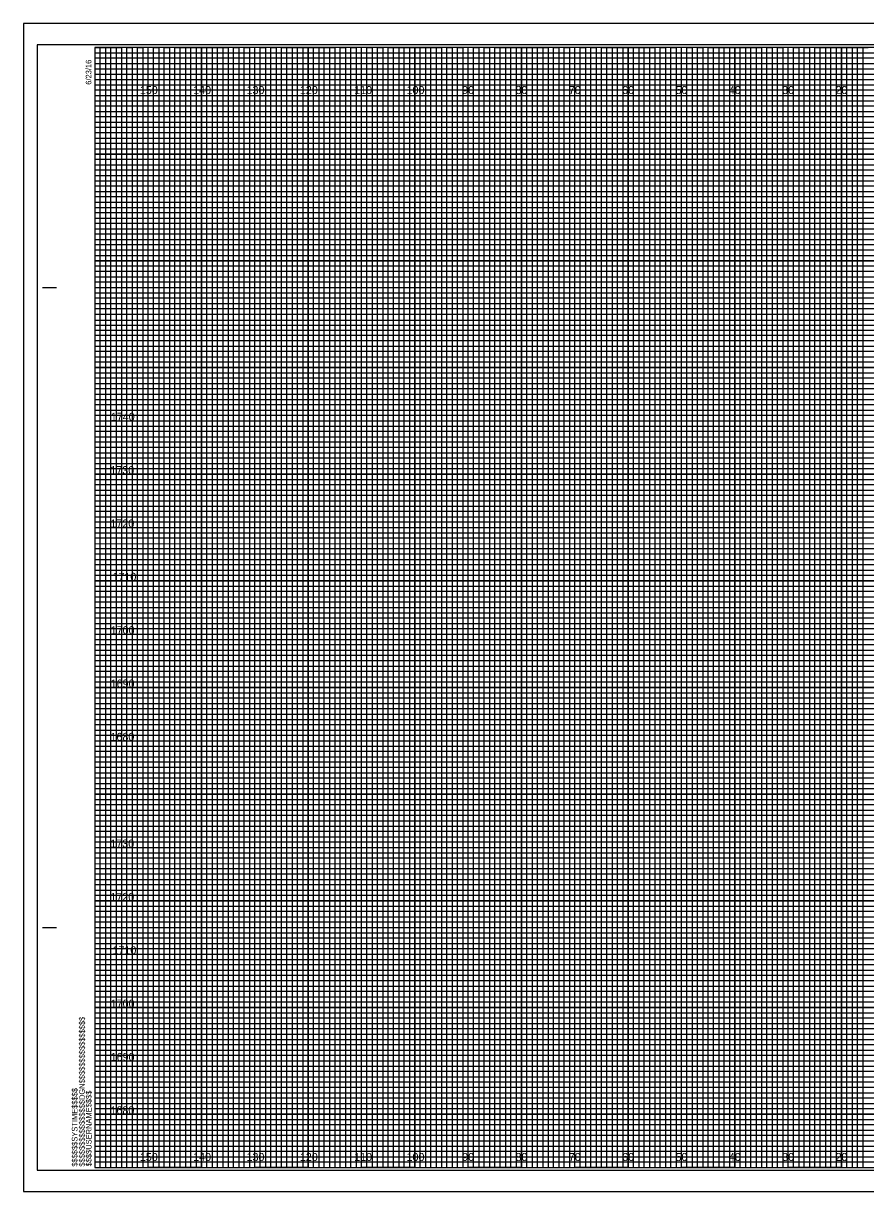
# Model space of a CAD drawing. Extents: x 656 to 993, y -2 to 2857.
# Drawn here: x 656.3 to 814.2, y 2638.3 to 2857.3 of the extents above; entities that cross this region are included whole.
import ezdxf

# ---------------------------------------------------------------- set-up
doc = ezdxf.new("R2010")
doc.units = 0
for name, color, linetype in [('Prop RDY Alternate Text Blue', 7, 'Continuous'), ('Prop Retaining Wall', 7, 'Continuous'), ('Prop SS Cut Line', 7, 'Continuous'), ('Prop SS Fill Line', 7, 'Continuous'), ('Prop SS Transition Line', 7, 'Continuous'), ('Raster_Level_0', 7, 'Continuous'), ('Raster_Level_3', 7, 'Continuous'), ('Scratch_Level_3', 7, 'Continuous'), ('Scratch_Level_7', 7, 'Continuous'), ('Typical Guardrail CELL', 7, 'Continuous'), ('Typical Text Asphalt at Bridge Approach CELL', 7, 'Continuous')]:
    doc.layers.add(name, color=color, linetype=linetype)

msp = doc.modelspace()

# ---------------------------------------------------------------- linework, layer by layer
at = {"layer": 'Prop RDY Alternate Text Blue'}
for p, q in [((679.74, 2642.8), (679.74, 2852.8)), ((689.74, 2642.8), (689.74, 2852.8)), ((699.74, 2642.8), (699.74, 2852.8)), ((709.74, 2642.8), (709.74, 2852.8)), ((719.74, 2642.8), (719.74, 2852.8)), ((729.74, 2642.8), (729.74, 2852.8)), ((739.74, 2642.8), (739.74, 2852.8)), ((749.74, 2642.8), (749.74, 2852.8)), ((759.74, 2642.8), (759.74, 2852.8)), ((769.74, 2642.8), (769.74, 2852.8)), ((779.74, 2642.8), (779.74, 2852.8)), ((789.74, 2642.8), (789.74, 2852.8)), ((799.74, 2642.8), (799.74, 2852.8)), ((809.74, 2642.8), (809.74, 2852.8)), ((669.74, 2842.8), (989.74, 2842.8)), ((669.74, 2832.8), (989.74, 2832.8)), ((669.74, 2822.8), (989.74, 2822.8)), ((669.74, 2812.8), (989.74, 2812.8)), ((669.74, 2802.8), (989.74, 2802.8)), ((669.74, 2792.8), (989.74, 2792.8)), ((669.74, 2782.8), (989.74, 2782.8)), ((669.74, 2772.8), (989.74, 2772.8)), ((669.74, 2762.8), (989.74, 2762.8)), ((669.74, 2752.8), (989.74, 2752.8)), ((669.74, 2742.8), (989.74, 2742.8)), ((669.74, 2732.8), (989.74, 2732.8)), ((669.74, 2722.8), (989.74, 2722.8)), ((669.74, 2712.8), (989.74, 2712.8)), ((669.74, 2702.8), (989.74, 2702.8)), ((669.74, 2692.8), (989.74, 2692.8)), ((669.74, 2682.8), (989.74, 2682.8)), ((669.74, 2672.8), (989.74, 2672.8)), ((669.74, 2662.8), (989.74, 2662.8)), ((669.74, 2652.8), (989.74, 2652.8))]:
    msp.add_line(p, q, dxfattribs=at)
at = {"layer": 'Prop Retaining Wall'}
for p, q in [((659.94, 2807.8), (662.44, 2807.8)), ((660.04, 2807.8), (662.54, 2807.8)), ((659.94, 2687.8), (662.44, 2687.8)), ((660.04, 2687.8), (662.54, 2687.8)), ((669.74, 2642.8), (669.74, 2642.8)), ((669.74, 2642.8), (669.74, 2642.8)), ((669.74, 2642.8), (669.74, 2642.8)), ((669.74, 2642.8), (669.74, 2642.8)), ((669.74, 2642.8), (669.74, 2642.8)), ((669.74, 2642.8), (669.74, 2642.8)), ((669.74, 2642.8), (669.74, 2642.8))]:
    msp.add_line(p, q, dxfattribs=at)
msp.add_lwpolyline([(989.74, 2852.8), (669.74, 2852.8), (669.74, 2642.8), (989.74, 2642.8)], close=True, dxfattribs=at)
at = {"layer": 'Prop SS Cut Line'}
for points in [[(669.74, 2852.8), (674.74, 2852.8), (674.74, 2642.8), (684.74, 2642.8), (684.74, 2852.8), (694.74, 2852.8), (694.74, 2642.8), (704.74, 2642.8), (704.74, 2852.8), (714.74, 2852.8), (714.74, 2642.8), (724.74, 2642.8), (724.74, 2852.8), (734.74, 2852.8), (734.74, 2642.8), (744.74, 2642.8), (744.74, 2852.8), (754.74, 2852.8), (754.74, 2642.8), (764.74, 2642.8), (764.74, 2852.8), (774.74, 2852.8), (774.74, 2642.8), (784.74, 2642.8), (784.74, 2852.8), (794.74, 2852.8), (794.74, 2642.8), (804.74, 2642.8), (804.74, 2852.8), (814.74, 2852.8)], [(669.74, 2847.8), (944.74, 2847.8)], [(669.74, 2827.8), (989.74, 2827.8), (989.74, 2837.8), (669.74, 2837.8)], [(669.74, 2807.8), (989.74, 2807.8), (989.74, 2817.8), (669.74, 2817.8)], [(669.74, 2787.8), (989.74, 2787.8), (989.74, 2797.8), (669.74, 2797.8)], [(669.74, 2767.8), (989.74, 2767.8), (989.74, 2777.8), (669.74, 2777.8)], [(669.74, 2747.8), (989.74, 2747.8), (989.74, 2757.8), (669.74, 2757.8)], [(669.74, 2727.8), (989.74, 2727.8), (989.74, 2737.8), (669.74, 2737.8)], [(669.74, 2707.8), (989.74, 2707.8), (989.74, 2717.8), (669.74, 2717.8)], [(669.74, 2687.8), (989.74, 2687.8), (989.74, 2697.8), (669.74, 2697.8)], [(669.74, 2667.8), (989.74, 2667.8), (989.74, 2677.8), (669.74, 2677.8)], [(669.74, 2647.8), (989.74, 2647.8), (989.74, 2657.8), (669.74, 2657.8)]]:
    msp.add_lwpolyline(points, dxfattribs=at)
at = {"layer": 'Prop SS Fill Line'}
for p, q in [((679.74, 2852.8), (669.74, 2852.8)), ((679.74, 2642.8), (679.74, 2852.8)), ((699.74, 2852.8), (689.74, 2852.8)), ((689.74, 2852.8), (689.74, 2642.8)), ((699.74, 2642.8), (699.74, 2852.8)), ((719.74, 2852.8), (709.74, 2852.8)), ((709.74, 2852.8), (709.74, 2642.8)), ((719.74, 2642.8), (719.74, 2852.8)), ((739.74, 2852.8), (729.74, 2852.8)), ((729.74, 2852.8), (729.74, 2642.8)), ((739.74, 2642.8), (739.74, 2852.8)), ((759.74, 2852.8), (749.74, 2852.8)), ((749.74, 2852.8), (749.74, 2642.8)), ((759.74, 2642.8), (759.74, 2852.8)), ((779.74, 2852.8), (769.74, 2852.8)), ((769.74, 2852.8), (769.74, 2642.8)), ((779.74, 2642.8), (779.74, 2852.8)), ((799.74, 2852.8), (789.74, 2852.8)), ((789.74, 2852.8), (789.74, 2642.8)), ((799.74, 2642.8), (799.74, 2852.8)), ((819.74, 2852.8), (809.74, 2852.8)), ((809.74, 2852.8), (809.74, 2642.8)), ((689.74, 2642.8), (679.74, 2642.8)), ((709.74, 2642.8), (699.74, 2642.8)), ((729.74, 2642.8), (719.74, 2642.8)), ((749.74, 2642.8), (739.74, 2642.8)), ((769.74, 2642.8), (759.74, 2642.8)), ((789.74, 2642.8), (779.74, 2642.8)), ((809.74, 2642.8), (799.74, 2642.8))]:
    msp.add_line(p, q, dxfattribs=at)
for points in [[(669.74, 2842.8), (989.74, 2842.8), (989.74, 2832.8), (669.74, 2832.8)], [(669.74, 2822.8), (989.74, 2822.8), (989.74, 2812.8), (669.74, 2812.8)], [(669.74, 2802.8), (989.74, 2802.8), (989.74, 2792.8), (669.74, 2792.8)], [(669.74, 2782.8), (989.74, 2782.8), (989.74, 2772.8), (669.74, 2772.8)], [(669.74, 2762.8), (989.74, 2762.8), (989.74, 2752.8), (669.74, 2752.8)], [(669.74, 2742.8), (989.74, 2742.8), (989.74, 2732.8), (669.74, 2732.8)], [(669.74, 2722.8), (989.74, 2722.8), (989.74, 2712.8), (669.74, 2712.8)], [(669.74, 2702.8), (989.74, 2702.8), (989.74, 2692.8), (669.74, 2692.8)], [(669.74, 2682.8), (989.74, 2682.8), (989.74, 2672.8), (669.74, 2672.8)], [(669.74, 2662.8), (989.74, 2662.8), (989.74, 2652.8), (669.74, 2652.8)]]:
    msp.add_lwpolyline(points, dxfattribs=at)
at = {"layer": 'Prop SS Transition Line'}
for p, q in [((669.74, 2851.8), (929.74, 2851.8)), ((929.74, 2850.78), (669.74, 2850.78)), ((669.74, 2850.78), (669.74, 2849.8)), ((669.74, 2849.8), (929.74, 2849.8)), ((929.74, 2848.69), (669.74, 2848.69)), ((669.74, 2848.69), (669.74, 2846.8)), ((669.74, 2846.8), (989.74, 2846.8))]:
    msp.add_line(p, q, dxfattribs=at)
for points in [[(669.74, 2845.8), (939.74, 2845.8), (989.74, 2845.8), (989.74, 2844.8), (669.74, 2844.8)], [(669.74, 2843.8), (989.74, 2843.8), (989.74, 2841.8), (669.74, 2841.8)], [(669.74, 2840.8), (989.74, 2840.8), (989.74, 2839.8), (669.74, 2839.78)], [(669.74, 2838.8), (989.74, 2838.8), (989.74, 2836.8), (669.74, 2836.8)], [(669.74, 2835.8), (989.74, 2835.8), (989.74, 2834.8), (669.74, 2834.8)], [(669.74, 2833.8), (989.74, 2833.8), (989.74, 2831.8), (669.74, 2831.8)], [(669.74, 2830.8), (989.74, 2830.8), (989.74, 2829.8), (669.74, 2829.8)], [(669.74, 2828.8), (989.74, 2828.8), (989.74, 2826.8), (669.74, 2826.8)], [(669.74, 2825.8), (989.74, 2825.8), (989.74, 2824.8), (669.74, 2824.8)], [(669.74, 2823.8), (989.74, 2823.8), (989.74, 2821.8), (669.74, 2821.8)], [(669.74, 2820.8), (989.74, 2820.8), (989.74, 2819.8), (669.74, 2819.8)], [(669.74, 2818.8), (989.74, 2818.8), (989.74, 2816.75), (989.74, 2815.8), (989.74, 2814.8), (669.74, 2814.8)], [(669.74, 2816.8), (989.74, 2816.8), (989.74, 2815.8), (669.74, 2815.8)], [(669.74, 2813.8), (989.74, 2813.8), (989.74, 2811.8), (669.74, 2811.83)], [(669.74, 2811.83), (989.74, 2811.8), (989.74, 2810.8), (669.74, 2810.8)], [(669.74, 2809.8), (989.74, 2809.8), (989.74, 2808.8), (669.74, 2808.8)], [(669.74, 2806.8), (989.74, 2806.8), (989.74, 2805.8), (669.74, 2805.8)], [(669.74, 2804.8), (989.74, 2804.8), (989.74, 2803.8), (669.74, 2803.8)], [(669.67, 2801.69), (989.74, 2801.69), (989.74, 2800.68), (669.67, 2800.68)], [(669.74, 2799.8), (989.74, 2799.8), (989.74, 2798.8), (669.74, 2798.8)], [(669.74, 2796.8), (989.74, 2796.8), (989.74, 2795.8), (669.74, 2795.8)], [(669.74, 2794.8), (989.74, 2794.8), (989.74, 2793.8), (669.74, 2793.8)], [(669.74, 2791.8), (989.74, 2791.8), (989.74, 2790.8), (669.74, 2790.8)], [(669.74, 2789.8), (989.74, 2789.8), (989.74, 2788.8), (669.74, 2788.8)], [(669.74, 2786.8), (989.74, 2786.8), (989.74, 2785.8), (669.74, 2785.8)], [(669.74, 2784.8), (989.74, 2784.8), (989.74, 2783.8), (669.74, 2783.8)], [(669.74, 2781.8), (989.74, 2781.8), (989.73, 2780.78), (669.74, 2780.8)], [(669.74, 2779.8), (989.74, 2779.8), (989.74, 2778.8), (669.74, 2778.8)], [(669.74, 2776.8), (989.74, 2776.8), (989.74, 2775.8), (669.74, 2775.8)], [(669.74, 2774.8), (989.74, 2774.8), (989.74, 2773.8), (669.74, 2773.8)], [(669.74, 2771.8), (989.74, 2771.8), (989.74, 2770.8), (669.74, 2770.8)], [(669.74, 2769.8), (989.74, 2769.8), (989.74, 2768.8), (669.74, 2768.8)], [(669.74, 2766.8), (989.74, 2766.8), (989.74, 2765.8), (669.74, 2765.8)], [(669.74, 2764.8), (989.74, 2764.8), (989.74, 2763.8), (669.74, 2763.8)], [(669.74, 2761.8), (989.74, 2761.8), (989.74, 2760.8), (669.74, 2760.8)], [(669.74, 2759.79), (989.81, 2759.71), (989.74, 2758.8), (669.74, 2758.8)], [(669.74, 2756.8), (989.74, 2756.8), (989.74, 2755.8), (669.74, 2755.8)], [(669.74, 2754.8), (989.74, 2754.8), (989.74, 2753.8), (669.74, 2753.8)], [(669.74, 2751.8), (989.74, 2751.8), (989.74, 2750.8), (669.74, 2750.8)], [(669.74, 2749.8), (989.74, 2749.8), (989.74, 2748.8), (669.74, 2748.8)], [(669.74, 2746.8), (989.74, 2746.8), (989.74, 2745.8), (669.74, 2745.8)], [(669.74, 2744.8), (989.74, 2744.8), (989.74, 2743.8), (669.74, 2743.8)], [(669.74, 2741.8), (989.74, 2741.8), (989.74, 2740.8), (669.74, 2740.8)], [(669.74, 2739.8), (989.74, 2739.8), (989.74, 2738.8), (669.74, 2738.8)], [(669.74, 2736.8), (989.74, 2736.8), (989.74, 2735.8), (669.74, 2735.8)], [(669.74, 2734.8), (989.74, 2734.8), (989.74, 2733.8), (669.74, 2733.8)], [(669.74, 2731.8), (989.74, 2731.8), (989.74, 2730.8), (669.74, 2730.8)], [(669.74, 2729.8), (989.74, 2729.8), (989.74, 2728.8), (669.74, 2728.8)], [(669.74, 2726.8), (989.74, 2726.8), (989.74, 2725.8), (669.74, 2725.8)], [(669.74, 2724.8), (989.74, 2724.8), (989.74, 2723.8), (669.74, 2723.8)], [(669.74, 2721.8), (989.74, 2721.8), (989.73, 2720.78), (669.74, 2720.8)], [(669.74, 2719.8), (989.74, 2719.8), (989.74, 2718.8), (669.74, 2718.8)], [(669.74, 2716.8), (989.74, 2716.8), (989.74, 2715.8), (669.74, 2715.8)], [(669.74, 2714.8), (989.74, 2714.8), (989.74, 2713.8), (669.74, 2713.8)], [(669.74, 2711.8), (989.74, 2711.8), (989.74, 2710.8), (669.74, 2710.8)], [(669.74, 2709.8), (989.74, 2709.8), (989.74, 2708.8), (669.74, 2708.8)], [(669.74, 2706.8), (989.74, 2706.8), (989.74, 2705.8), (669.74, 2705.8)], [(669.74, 2704.8), (989.74, 2704.8), (989.74, 2703.8), (669.74, 2703.8)], [(669.74, 2701.8), (989.74, 2701.8), (989.74, 2700.8), (669.74, 2700.8)], [(669.74, 2699.79), (989.81, 2699.71), (989.74, 2698.8), (669.74, 2698.8)], [(669.74, 2696.8), (989.74, 2696.8), (989.74, 2695.8), (669.74, 2695.8)], [(669.74, 2694.8), (989.74, 2694.8), (989.74, 2693.8), (669.74, 2693.8)], [(669.74, 2691.8), (989.74, 2691.8), (989.74, 2690.8), (669.74, 2690.8)], [(669.74, 2689.8), (989.74, 2689.8), (989.74, 2688.8), (669.74, 2688.8)], [(669.74, 2686.8), (989.74, 2686.8), (989.74, 2685.8), (669.74, 2685.8)], [(669.74, 2684.8), (989.74, 2684.8), (989.74, 2683.8), (669.74, 2683.8)], [(669.74, 2681.8), (989.74, 2681.8), (989.74, 2680.8), (669.74, 2680.8)], [(669.74, 2679.8), (989.74, 2679.8), (989.74, 2678.8), (669.74, 2678.8)], [(669.74, 2676.8), (989.74, 2676.8), (989.74, 2675.8), (669.74, 2675.8)], [(669.74, 2674.8), (989.74, 2674.8), (989.74, 2673.8), (669.74, 2673.8)], [(669.74, 2671.8), (989.74, 2671.8), (989.74, 2670.8), (669.74, 2670.8)], [(669.74, 2669.8), (989.74, 2669.8), (989.74, 2668.8), (669.74, 2668.8)], [(669.74, 2666.8), (989.74, 2666.8), (989.74, 2665.8), (669.74, 2665.8)], [(669.74, 2664.8), (989.74, 2664.8), (989.74, 2663.8), (669.74, 2663.8)], [(669.74, 2661.8), (989.74, 2661.8), (989.74, 2660.8), (669.74, 2660.8)], [(669.74, 2659.8), (989.74, 2659.8), (989.74, 2658.8), (669.74, 2658.8)], [(669.74, 2656.8), (989.74, 2656.8), (989.74, 2655.8), (669.74, 2655.8)], [(669.74, 2654.8), (989.74, 2654.8), (989.74, 2653.8), (669.74, 2653.8)], [(669.74, 2651.8), (989.74, 2651.8), (989.74, 2650.8), (669.74, 2650.8)], [(669.74, 2649.8), (989.74, 2649.8), (989.74, 2648.8), (669.74, 2648.8)], [(669.74, 2646.8), (989.74, 2646.8), (989.74, 2645.8), (669.74, 2645.8)], [(669.74, 2644.8), (989.74, 2644.8), (989.74, 2643.8), (669.74, 2643.8)]]:
    msp.add_lwpolyline(points, dxfattribs=at)
at = {"layer": 'Raster_Level_3'}
for points in [[(669.74, 2642.8), (670.74, 2642.8), (670.74, 2852.8), (671.74, 2852.8), (671.74, 2642.8)], [(671.74, 2642.8), (672.74, 2642.8), (672.74, 2852.8), (673.74, 2852.8), (673.74, 2642.8)], [(674.74, 2642.8), (675.74, 2642.8), (675.74, 2852.8), (676.74, 2852.8), (676.74, 2642.8)], [(676.74, 2642.8), (677.74, 2642.8), (677.74, 2852.8), (678.74, 2852.8), (678.74, 2642.8)], [(679.74, 2642.8), (680.74, 2642.8), (680.74, 2852.8), (681.74, 2852.8), (681.74, 2642.8)], [(681.74, 2642.8), (682.74, 2642.8), (682.74, 2852.8), (683.74, 2852.8), (683.74, 2642.8)], [(684.74, 2642.8), (685.74, 2642.8), (685.74, 2852.8), (686.74, 2852.8), (686.74, 2642.8)], [(686.74, 2642.8), (687.74, 2642.8), (687.74, 2852.8), (688.74, 2852.8), (688.74, 2642.8)], [(689.74, 2642.8), (690.74, 2642.8), (690.74, 2852.8), (691.74, 2852.8), (691.74, 2642.8)], [(691.74, 2642.8), (692.74, 2642.8), (692.74, 2852.8), (693.74, 2852.8), (693.74, 2642.8)], [(694.74, 2642.8), (695.74, 2642.8), (695.74, 2852.8), (696.74, 2852.8), (696.74, 2642.8)], [(696.74, 2642.8), (697.74, 2642.8), (697.74, 2852.8), (698.74, 2852.8), (698.74, 2642.8)], [(699.74, 2642.8), (700.74, 2642.8), (700.74, 2852.8), (701.74, 2852.8), (701.74, 2642.8)], [(701.74, 2642.8), (702.74, 2642.8), (702.74, 2852.8), (703.74, 2852.8), (703.74, 2642.8)], [(704.74, 2642.8), (705.74, 2642.8), (705.74, 2852.8), (706.74, 2852.8), (706.74, 2642.8)], [(706.74, 2642.8), (707.74, 2642.8), (707.74, 2852.8), (708.74, 2852.8), (708.74, 2642.8)], [(709.74, 2642.8), (710.74, 2642.8), (710.74, 2852.8), (711.74, 2852.8), (711.74, 2642.8)], [(711.74, 2642.8), (712.74, 2642.8), (712.74, 2852.8), (713.74, 2852.8), (713.74, 2642.8)], [(714.74, 2642.8), (715.74, 2642.8), (715.74, 2852.8), (716.74, 2852.8), (716.74, 2642.8)], [(716.74, 2642.8), (717.74, 2642.8), (717.74, 2852.8), (718.74, 2852.8), (718.74, 2642.8)], [(719.74, 2642.8), (720.74, 2642.8), (720.74, 2852.8), (721.74, 2852.8), (721.74, 2642.8)], [(721.74, 2642.8), (722.74, 2642.8), (722.74, 2852.8), (723.74, 2852.8), (723.74, 2642.8)], [(724.74, 2642.8), (725.74, 2642.8), (725.74, 2852.8), (726.74, 2852.8), (726.74, 2642.8)], [(726.74, 2642.8), (727.74, 2642.8), (727.74, 2852.8), (728.74, 2852.8), (728.74, 2642.8)], [(729.74, 2642.8), (730.74, 2642.8), (730.74, 2852.8), (731.74, 2852.8), (731.74, 2642.8)], [(731.74, 2642.8), (732.74, 2642.8), (732.74, 2852.8), (733.74, 2852.8), (733.74, 2642.8)], [(734.74, 2642.8), (735.74, 2642.8), (735.74, 2852.8), (736.74, 2852.8), (736.74, 2642.8)], [(736.74, 2642.8), (737.74, 2642.8), (737.74, 2852.8), (738.74, 2852.8), (738.74, 2642.8)], [(739.74, 2642.8), (740.74, 2642.8), (740.74, 2852.8), (741.74, 2852.8), (741.74, 2642.8)], [(741.74, 2642.8), (742.74, 2642.8), (742.74, 2852.8), (743.74, 2852.8), (743.74, 2642.8)], [(744.74, 2642.8), (745.74, 2642.8), (745.74, 2852.8), (746.74, 2852.8), (746.74, 2642.8)], [(746.74, 2642.8), (747.74, 2642.8), (747.74, 2852.8), (748.74, 2852.8), (748.74, 2642.8)], [(749.74, 2642.8), (750.74, 2642.8), (750.74, 2852.8), (751.74, 2852.8), (751.74, 2642.8)], [(751.74, 2642.8), (752.74, 2642.8), (752.74, 2852.8), (753.74, 2852.8), (753.74, 2642.8)], [(754.74, 2642.8), (755.74, 2642.8), (755.74, 2852.8), (756.74, 2852.8), (756.74, 2642.8)], [(756.74, 2642.8), (757.74, 2642.8), (757.74, 2852.8), (758.74, 2852.8), (758.74, 2642.8)], [(759.74, 2642.8), (760.74, 2642.8), (760.74, 2852.8), (761.74, 2852.8), (761.74, 2642.8)], [(761.74, 2642.8), (762.74, 2642.8), (762.74, 2852.8), (763.74, 2852.8), (763.74, 2642.8)], [(764.74, 2642.8), (765.74, 2642.8), (765.74, 2852.8), (766.74, 2852.8), (766.74, 2642.8)], [(766.74, 2642.8), (767.74, 2642.8), (767.74, 2852.8), (768.74, 2852.8), (768.74, 2642.8)], [(769.74, 2642.8), (770.74, 2642.8), (770.74, 2852.8), (771.74, 2852.8), (771.74, 2642.8)], [(771.74, 2642.8), (772.74, 2642.8), (772.74, 2852.8), (773.74, 2852.8), (773.74, 2642.8)], [(774.74, 2642.8), (775.74, 2642.8), (775.74, 2852.8), (776.74, 2852.8), (776.74, 2642.8)], [(776.74, 2642.8), (777.74, 2642.8), (777.74, 2852.8), (778.74, 2852.8), (778.74, 2642.8)], [(779.74, 2642.8), (780.74, 2642.8), (780.74, 2852.8), (781.74, 2852.8), (781.74, 2642.8)], [(781.74, 2642.8), (782.74, 2642.8), (782.74, 2852.8), (783.74, 2852.8), (783.74, 2642.8)], [(784.74, 2642.8), (785.74, 2642.8), (785.74, 2852.8), (786.74, 2852.8), (786.74, 2642.8)], [(786.74, 2642.8), (787.74, 2642.8), (787.74, 2852.8), (788.74, 2852.8), (788.74, 2642.8)], [(789.74, 2642.8), (790.74, 2642.8), (790.74, 2852.8), (791.74, 2852.8), (791.74, 2642.8)], [(791.74, 2642.8), (792.74, 2642.8), (792.74, 2852.8), (793.74, 2852.8), (793.74, 2642.8)], [(794.74, 2642.8), (795.74, 2642.8), (795.74, 2852.8), (796.74, 2852.8), (796.74, 2642.8)], [(796.74, 2642.8), (797.74, 2642.8), (797.74, 2852.8), (798.74, 2852.8), (798.74, 2642.8)], [(799.74, 2642.8), (800.74, 2642.8), (800.74, 2852.8), (801.74, 2852.8), (801.74, 2642.8)], [(801.74, 2642.8), (802.74, 2642.8), (802.74, 2852.8), (803.74, 2852.8), (803.74, 2642.8)], [(804.74, 2642.8), (805.74, 2642.8), (805.74, 2852.8), (806.74, 2852.8), (806.74, 2642.8)], [(806.74, 2642.8), (807.74, 2642.8), (807.74, 2852.8), (808.74, 2852.8), (808.74, 2642.8)], [(809.74, 2642.8), (810.74, 2642.8), (810.74, 2852.8), (811.74, 2852.8), (811.74, 2642.8)], [(811.74, 2642.8), (812.74, 2642.8), (812.74, 2852.8), (813.74, 2852.8), (813.74, 2642.8)]]:
    msp.add_lwpolyline(points, dxfattribs=at)
at = {"layer": 'Scratch_Level_7'}
msp.add_lwpolyline([(656.34, 2638.3), (993.04, 2638.3), (993.04, 2857.3), (656.34, 2857.3)], close=True, dxfattribs=at)
at = {"layer": 'Typical Guardrail CELL'}
msp.add_lwpolyline([(658.94, 2642.3), (992.14, 2642.3), (992.14, 2853.3), (658.94, 2853.3)], close=True, dxfattribs=at)
at = {"layer": 'Typical Text Asphalt at Bridge Approach CELL'}
for p, q in [((993.04, 2857.3), (656.34, 2857.3)), ((656.34, 2857.3), (656.34, 2638.3)), ((656.34, 2638.3), (993.04, 2638.3))]:
    msp.add_line(p, q, dxfattribs=at)

# ---------------------------------------------------------------- texts
at = {"layer": 'Prop Retaining Wall'}
for s, p in [('6/23/16', (669.09, 2845.8)), ('$$$$$$$$$$$$$$$$DGN$$$$$$$$$$$$$$$$', (667.86, 2642.98)), ('$$$$$$SYSTIME$$$$$', (666.48, 2642.98)), ('$$$$USERNAME$$$$', (669.12, 2643.03))]:
    msp.add_text(s, height=1.05, rotation=90, dxfattribs=at).set_placement(p)
at = {"layer": 'Raster_Level_0'}
for s, p in [('150', (678.18, 2844.05)), ('140', (688.18, 2844.05)), ('130', (698.18, 2844.05)), ('120', (708.18, 2844.05)), ('110', (718.36, 2844.05)), ('100', (728.18, 2844.05)), ('90', (738.6, 2844.05)), ('80', (748.6, 2844.05)), ('70', (758.6, 2844.05)), ('60', (768.6, 2844.05)), ('50', (778.6, 2844.05)), ('40', (788.6, 2844.05)), ('30', (798.6, 2844.05)), ('20', (808.6, 2844.05)), ('150', (678.18, 2644.05)), ('140', (688.18, 2644.05)), ('130', (698.18, 2644.05)), ('120', (708.18, 2644.05)), ('110', (718.36, 2644.05)), ('100', (728.18, 2644.05)), ('90', (738.6, 2644.05)), ('80', (748.6, 2644.05)), ('70', (758.6, 2644.05)), ('60', (768.6, 2644.05)), ('50', (778.6, 2644.05)), ('40', (788.6, 2644.05)), ('30', (798.6, 2644.05)), ('20', (808.6, 2644.05))]:
    msp.add_text(s, height=1.5, dxfattribs=at).set_placement(p)
at = {"layer": 'Scratch_Level_3'}
for s, p in [('1740', (672.74, 2782.8)), ('1730', (672.66, 2772.8)), ('1720', (672.67, 2762.8)), ('1710', (673.05, 2752.8)), ('1700', (672.72, 2742.8)), ('1690', (672.71, 2732.8)), ('1680', (672.68, 2722.8)), ('1730', (672.66, 2702.8)), ('1720', (672.67, 2692.8)), ('1710', (673.05, 2682.8)), ('1700', (672.72, 2672.8)), ('1690', (672.71, 2662.8)), ('1680', (672.68, 2652.8))]:
    msp.add_text(s, height=1.5, dxfattribs=at).set_placement(p)

doc.saveas('drawing.dxf')
